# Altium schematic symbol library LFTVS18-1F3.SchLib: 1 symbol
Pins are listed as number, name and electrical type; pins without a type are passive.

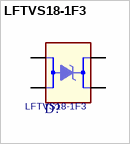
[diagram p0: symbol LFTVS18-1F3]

## LFTVS18-1F3
designator D?
footprint ST_CSP04N40P2X2_77X77X61
pins: A1 K1, A2 K2, B1 A1, B2 A2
